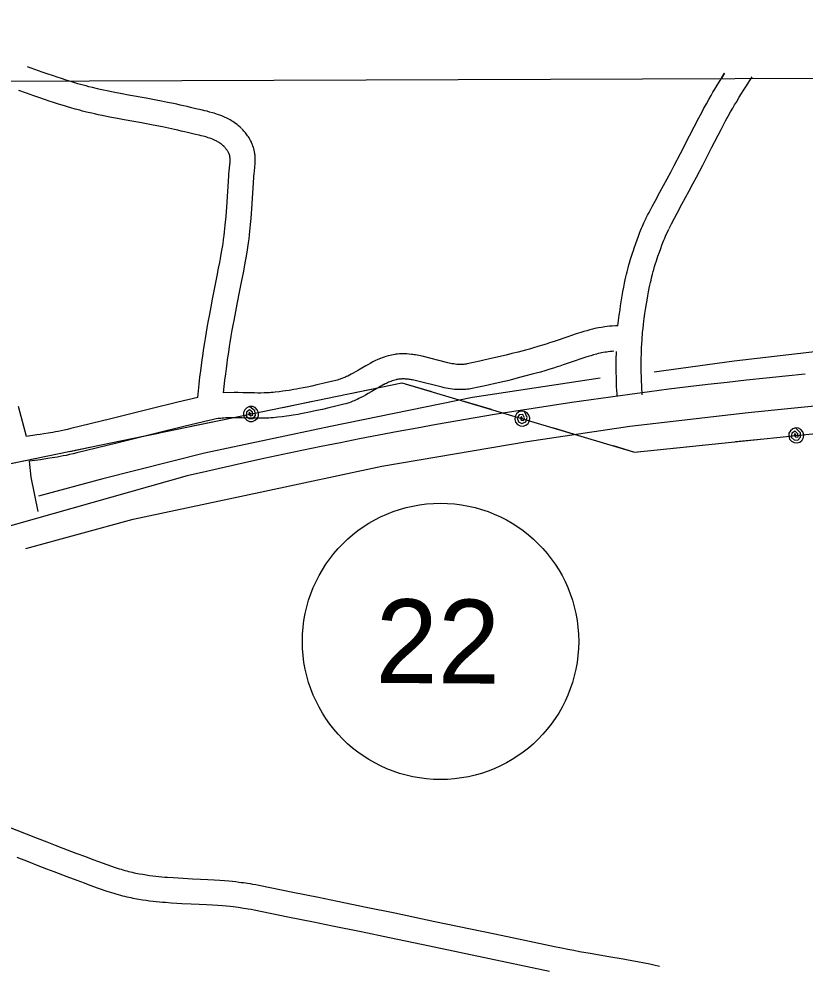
# Model space of a CAD drawing. Extents: x 3392644 to 3430565, y 576657 to 602123.
# Drawn here: x 3407890 to 3408829, y 599212 to 600343 of the extents above; entities that cross this region are included whole.
import ezdxf

# ---------------------------------------------------------------- set-up
doc = ezdxf.new("R2010")
doc.units = 0
for name, color, linetype in [('V-GRID-FRAM', 7, 'Continuous'), ('V-ROAD-CNTR', 7, 'Continuous'), ('V-ROAD-IDEN', 7, 'Continuous'), ('V-TOPO-SHOR', 7, 'Continuous'), ('V-UTIL-LINE', 7, 'Continuous')]:
    doc.layers.add(name, color=color, linetype=linetype)

msp = doc.modelspace()

# ---------------------------------------------------------------- linework, layer by layer
at = {"layer": 'V-GRID-FRAM'}
msp.add_lwpolyline([(3396720.3, 600227.7), (3428325.7, 600342.6), (3428399.7, 582159.3), (3396778.5, 582044.3), (3396720.3, 600227.7)], dxfattribs=at)
at = {"layer": 'V-ROAD-CNTR'}
for points in [[(3408156.2, 600211.8), (3408154.6, 600213.4), (3408152.8, 600215), (3408151, 600216.4), (3408149.3, 600217.7), (3408147.6, 600219), (3408145.9, 600220.1), (3408144.3, 600221.1), (3408142.7, 600222.1), (3408141.1, 600222.9), (3408139.6, 600223.7), (3408138.1, 600224.5), (3408136.7, 600225.1), (3408135.3, 600225.8), (3408132.7, 600226.9), (3408130.2, 600227.8), (3408127.8, 600228.7), (3408125.7, 600229.4), (3408123.6, 600230), (3408121.7, 600230.6), (3408118.2, 600231.5), (3408115.2, 600232.3), (3408112.6, 600232.9), (3408108.1, 600233.9), (3408101.7, 600235.3), (3408098.6, 600236.1), (3408095.5, 600236.8), (3408091.2, 600237.9), (3408087, 600238.9), (3408082.9, 600239.8), (3408079, 600240.7), (3408075.2, 600241.5), (3408067.8, 600243), (3408060.9, 600244.4), (3408054.4, 600245.7), (3408042.4, 600247.9), (3408021.5, 600251.7), (3408013.7, 600253.1), (3408006.9, 600254.4), (3408001.1, 600255.6), (3407995.9, 600256.7), (3407991.5, 600257.6), (3407987.6, 600258.5), (3407984.2, 600259.2), (3407978.3, 600260.6), (3407973.9, 600261.7), (3407970.6, 600262.6), (3407965.7, 600263.9), (3407960.8, 600265.3), (3407957.1, 600266.4), (3407953.6, 600267.4), (3407946.9, 600269.5), (3407941.2, 600271.4), (3407936.1, 600273), (3407931.7, 600274.5), (3407924, 600277.2), (3407918.2, 600279.2), (3407909.5, 600282.3), (3407900.8, 600285.5)], [(3408639.8, 600105.1), (3408641.3, 600108.2), (3408643.1, 600111.6), (3408646.8, 600118.8), (3408650.2, 600125), (3408656, 600135.7), (3408664.6, 600151.7), (3408668.9, 600159.7), (3408673.1, 600167.7), (3408680.5, 600181.8), (3408691.5, 600203.2), (3408702.6, 600224.6), (3408704.5, 600228.3), (3408706.4, 600231.8), (3408708.1, 600235.1), (3408711.5, 600241.2), (3408714.4, 600246.5), (3408717.1, 600251.1), (3408719.4, 600255.1), (3408721.5, 600258.6), (3408725.2, 600264.7), (3408728, 600269.2), (3408730.1, 600272.6), (3408733.3, 600277.7), (3408729.6, 600272)], [(3408667.4, 600093.2), (3408668.1, 600094.7), (3408669.7, 600097.8), (3408673.3, 600104.7), (3408676.6, 600110.8), (3408682.3, 600121.4), (3408691, 600137.5), (3408695.4, 600145.6), (3408699.7, 600153.8), (3408707.1, 600168), (3408718.2, 600189.4), (3408729.2, 600210.8), (3408731.1, 600214.4), (3408732.8, 600217.7), (3408734.5, 600220.8), (3408737.7, 600226.6), (3408740.5, 600231.7), (3408743.1, 600236.1), (3408745.3, 600239.9), (3408747.3, 600243.2), (3408750.8, 600249.1), (3408753.5, 600253.4), (3408755.5, 600256.7), (3408758.6, 600261.5), (3408766.3, 600273.6)], [(3408135.4, 600190.2), (3408134.3, 600191.3), (3408133.3, 600192.1), (3408132.4, 600192.9), (3408131.4, 600193.6), (3408130.5, 600194.3), (3408129.6, 600194.9), (3408128.7, 600195.5), (3408127.7, 600196), (3408126.8, 600196.5), (3408125.9, 600197), (3408125, 600197.5), (3408124.1, 600197.9), (3408123.3, 600198.3), (3408121.5, 600199), (3408119.8, 600199.7), (3408118.1, 600200.3), (3408116.5, 600200.8), (3408115, 600201.3), (3408113.5, 600201.7), (3408110.6, 600202.5), (3408108.1, 600203.1), (3408105.8, 600203.7), (3408101.5, 600204.6), (3408095, 600206.1), (3408091.7, 600206.9), (3408088.3, 600207.7), (3408084.2, 600208.7), (3408080.2, 600209.7), (3408076.3, 600210.5), (3408072.6, 600211.4), (3408068.9, 600212.2), (3408061.8, 600213.6), (3408055.1, 600215), (3408048.9, 600216.2), (3408037, 600218.4), (3408016, 600222.2), (3408008.1, 600223.7), (3408001.2, 600225), (3407995.1, 600226.2), (3407989.8, 600227.3), (3407985.1, 600228.3), (3407981, 600229.2), (3407977.5, 600230), (3407971.2, 600231.5), (3407966.5, 600232.6), (3407963, 600233.6), (3407957.7, 600235), (3407952.5, 600236.5), (3407948.5, 600237.6), (3407944.8, 600238.8), (3407937.9, 600240.9), (3407931.9, 600242.8), (3407926.6, 600244.6), (3407922, 600246.1), (3407914.1, 600248.8), (3407908.1, 600250.9), (3407899.3, 600254.1), (3407890.5, 600257.3)], [(3408134.7, 599896.3), (3408136.5, 599911.5), (3408137.4, 599918.9), (3408138.2, 599925.4), (3408139, 599931.1), (3408139.7, 599936.1), (3408141, 599944.9), (3408142, 599951.5), (3408142.8, 599956.4), (3408144.1, 599963.8), (3408145.3, 599971.2), (3408146.4, 599977.1), (3408147.4, 599982.6), (3408149.4, 599993.1), (3408151.1, 600002.2), (3408154.3, 600018.2), (3408156.7, 600030.2), (3408158.5, 600039.4), (3408159.7, 600046.2), (3408160.7, 600051.4), (3408162.1, 600059.2), (3408163.4, 600067.1), (3408163.8, 600069.9), (3408164.6, 600075.2), (3408165.3, 600080.2), (3408165.9, 600084.9), (3408166.3, 600089.2), (3408166.8, 600093.3), (3408167.1, 600097.2), (3408167.7, 600104.3), (3408168.2, 600110.5), (3408168.6, 600116), (3408170.9, 600153.2), (3408171.1, 600155.3), (3408171.3, 600157.3), (3408171.7, 600161.4), (3408172.2, 600165.2), (3408172.3, 600167.1), (3408172.5, 600168.8), (3408172.6, 600170.5), (3408172.7, 600172.2), (3408172.7, 600173.7), (3408172.7, 600175.3), (3408172.6, 600176.7), (3408172.6, 600178.1), (3408172.5, 600179.4), (3408172.3, 600180.7), (3408172.2, 600182), (3408171.8, 600184.1), (3408171.4, 600186.1), (3408170.9, 600187.9), (3408170.5, 600189.5), (3408170, 600190.9), (3408169.6, 600192.1), (3408169.1, 600193.2), (3408168.4, 600195), (3408167.7, 600196.4), (3408167.1, 600197.5), (3408166.3, 600199), (3408165.4, 600200.5), (3408164.5, 600201.8), (3408163.6, 600203.1), (3408162.7, 600204.3), (3408161.8, 600205.5), (3408160.9, 600206.6), (3408160, 600207.7), (3408159.1, 600208.8), (3408158.2, 600209.8), (3408157.3, 600210.7), (3408156.5, 600211.5)], [(3408104.1, 599890.8), (3408105.7, 599906.4), (3408106.2, 599910.8), (3408106.7, 599915), (3408107.6, 599922.6), (3408108.5, 599929.4), (3408109.3, 599935.3), (3408110, 599940.4), (3408111.3, 599949.4), (3408112.4, 599956.2), (3408113.2, 599961.2), (3408114.5, 599968.8), (3408115.8, 599976.3), (3408116.9, 599982.4), (3408117.9, 599988.1), (3408119.9, 599998.7), (3408121.7, 600008), (3408124.9, 600024), (3408127.3, 600036), (3408129, 600045), (3408130.2, 600051.7), (3408131.2, 600056.7), (3408132.5, 600064.3), (3408133.8, 600071.9), (3408134.2, 600074.4), (3408134.9, 600079.4), (3408135.5, 600084), (3408136.1, 600088.3), (3408136.5, 600092.4), (3408136.9, 600096.3), (3408137.2, 600099.9), (3408137.8, 600106.7), (3408138.3, 600112.7), (3408138.6, 600117.9), (3408141, 600155.4), (3408141.2, 600158.1), (3408141.4, 600160.6), (3408141.9, 600164.8), (3408142.3, 600168.3), (3408142.5, 600169.7), (3408142.6, 600170.9), (3408142.6, 600172), (3408142.7, 600173), (3408142.7, 600173.9), (3408142.7, 600174.8), (3408142.7, 600175.5), (3408142.6, 600176.1), (3408142.6, 600176.7), (3408142.5, 600177.3), (3408142.5, 600177.7), (3408142.3, 600178.7), (3408142.2, 600179.4), (3408142, 600180), (3408141.8, 600180.6), (3408141.7, 600181), (3408141.5, 600181.4), (3408141.4, 600181.7), (3408141.1, 600182.4), (3408140.9, 600182.9), (3408140.7, 600183.2), (3408140.4, 600183.8), (3408140, 600184.4), (3408139.6, 600185.1), (3408139.1, 600185.8), (3408138.6, 600186.5), (3408138.1, 600187.1), (3408137.6, 600187.7), (3408137.1, 600188.3), (3408136.7, 600188.9), (3408136.2, 600189.4), (3408135.7, 600189.9), (3408135.1, 600190.5)], [(3408605.9, 599976.3), (3408607.5, 599989), (3408608.4, 599995.3), (3408609.1, 600000.1), (3408610.2, 600007.2), (3408611.4, 600014.3), (3408611.9, 600017.2), (3408612.9, 600022.5), (3408613.8, 600027.1), (3408614.7, 600031.2), (3408615.5, 600034.8), (3408616.2, 600037.9), (3408616.9, 600040.6), (3408618.1, 600045.3), (3408619.1, 600048.9), (3408619.8, 600051.6), (3408621, 600055.6), (3408622.2, 600059.5), (3408623.3, 600062.9), (3408624.3, 600066), (3408625.2, 600068.9), (3408627.1, 600074.3), (3408628.8, 600079), (3408630.4, 600083.1), (3408631.8, 600086.7), (3408633, 600089.9), (3408634.2, 600092.6), (3408635.2, 600095), (3408637, 600099.2), (3408638.5, 600102.3), (3408639.6, 600104.7), (3408639.8, 600105.1)], [(3408636.4, 599977.9), (3408636.8, 599981.6), (3408637.3, 599985.1), (3408638.1, 599991.1), (3408638.8, 599995.6), (3408639.9, 600002.4), (3408641, 600009.3), (3408641.4, 600011.9), (3408642.4, 600016.8), (3408643.2, 600021.1), (3408644, 600024.8), (3408644.7, 600028.1), (3408645.4, 600030.9), (3408646, 600033.4), (3408647.1, 600037.7), (3408648, 600040.9), (3408648.6, 600043.3), (3408649.7, 600046.9), (3408650.8, 600050.6), (3408651.8, 600053.6), (3408652.8, 600056.5), (3408653.7, 600059.2), (3408655.4, 600064.3), (3408657, 600068.6), (3408658.4, 600072.4), (3408659.7, 600075.7), (3408660.8, 600078.5), (3408661.8, 600081), (3408662.7, 600083.1), (3408664.4, 600086.8), (3408665.7, 600089.6), (3408666.6, 600091.6), (3408666.6, 600091.7)], [(3408666.9, 600092.2), (3408667.4, 600093.2)], [(3408634.1, 599947.3), (3408634.2, 599950), (3408634.5, 599954.7), (3408634.7, 599959.5), (3408634.9, 599962.5), (3408635.2, 599965.4), (3408635.4, 599968.1), (3408635.9, 599973.3), (3408636.4, 599977.7), (3408636.4, 599977.9)], [(3408605.9, 599976.3), (3408602.8, 599976.2), (3408599, 599975.9), (3408595.8, 599975.6), (3408592.9, 599975.2), (3408590.4, 599974.9), (3408588.2, 599974.6), (3408586.2, 599974.3), (3408582.8, 599973.7), (3408580.2, 599973.2), (3408578.3, 599972.8), (3408575.4, 599972.1), (3408572.5, 599971.4), (3408568.6, 599970.4), (3408565, 599969.3), (3408561.7, 599968.3), (3408558.7, 599967.4), (3408555.8, 599966.5), (3408550.6, 599964.7), (3408546.1, 599963.2), (3408530.8, 599957.9), (3408527, 599956.6), (3408524.2, 599955.7), (3408520, 599954.3), (3408515.8, 599953), (3408510.2, 599951.4), (3408505, 599949.9), (3408500.1, 599948.5), (3408495.5, 599947.3), (3408486.8, 599944.9), (3408479.2, 599943), (3408472.5, 599941.3), (3408466.7, 599939.9), (3408461.6, 599938.7), (3408452.6, 599936.6), (3408445.9, 599935), (3408440.9, 599933.9), (3408433.3, 599932.3), (3408425.8, 599930.7), (3408424.8, 599930.5), (3408423.8, 599930.4), (3408422.9, 599930.3), (3408421.9, 599930.2), (3408421, 599930.1), (3408420.1, 599930), (3408419.1, 599930), (3408418.2, 599930), (3408417.2, 599930), (3408416.3, 599930), (3408415.4, 599930.1), (3408413.5, 599930.2), (3408411.6, 599930.4), (3408409.8, 599930.7), (3408408, 599931), (3408406.1, 599931.3), (3408404.4, 599931.6), (3408402.8, 599932), (3408372.2, 599939.9), (3408369.9, 599940.4), (3408367.9, 599940.8), (3408366, 599941.1), (3408364.2, 599941.5), (3408362.5, 599941.7), (3408360.9, 599941.9), (3408359.3, 599942.1), (3408356.5, 599942.4), (3408353.9, 599942.6), (3408351.7, 599942.7), (3408349.7, 599942.7), (3408347.9, 599942.7), (3408346.3, 599942.7), (3408344.9, 599942.6), (3408342.6, 599942.4), (3408340.8, 599942.2), (3408339.3, 599942), (3408337.3, 599941.7), (3408335.3, 599941.3), (3408333.8, 599940.9), (3408331.3, 599940.3), (3408328.8, 599939.5), (3408326.5, 599938.8), (3408324.3, 599938), (3408322.3, 599937.2)], [(3408601, 599945.9), (3408598.9, 599945.7), (3408596.5, 599945.4), (3408594.4, 599945.2), (3408592.6, 599944.9), (3408591, 599944.7), (3408588.2, 599944.2), (3408586.2, 599943.8), (3408584.7, 599943.5), (3408582.4, 599943), (3408580.1, 599942.4), (3408576.7, 599941.5), (3408573.5, 599940.5), (3408570.5, 599939.6), (3408567.7, 599938.8), (3408565.1, 599937.9), (3408560.2, 599936.3), (3408555.9, 599934.8), (3408540.5, 599929.5), (3408536.5, 599928.1), (3408533.5, 599927.1), (3408529, 599925.7), (3408524.4, 599924.3), (3408518.6, 599922.6), (3408513.2, 599921), (3408508.1, 599919.6), (3408503.3, 599918.3), (3408494.4, 599915.9), (3408486.6, 599913.9), (3408479.8, 599912.2), (3408473.8, 599910.7), (3408468.5, 599909.5), (3408459.3, 599907.3), (3408452.4, 599905.8), (3408447.3, 599904.6), (3408439.5, 599903), (3408431.7, 599901.3), (3408429.9, 599901), (3408428.2, 599900.7), (3408426.4, 599900.5), (3408424.7, 599900.3), (3408423, 599900.2), (3408421.4, 599900.1), (3408419.8, 599900), (3408418.2, 599900), (3408416.6, 599900), (3408415.1, 599900.1), (3408413.6, 599900.1), (3408410.8, 599900.3), (3408408.1, 599900.6), (3408405.5, 599901), (3408403, 599901.4), (3408400.6, 599901.8), (3408398.3, 599902.2), (3408395.9, 599902.8), (3408365.2, 599910.7), (3408363.7, 599911), (3408362.1, 599911.3), (3408360.7, 599911.6), (3408359.3, 599911.8), (3408358.1, 599912), (3408356.9, 599912.2), (3408355.9, 599912.3), (3408353.9, 599912.5), (3408352.2, 599912.6), (3408350.8, 599912.7), (3408349.6, 599912.7), (3408348.5, 599912.7), (3408347.6, 599912.7), (3408346.9, 599912.6), (3408345.5, 599912.5), (3408344.5, 599912.4), (3408343.8, 599912.3), (3408342.7, 599912.1), (3408341.6, 599911.9), (3408340.9, 599911.8), (3408339.3, 599911.3), (3408337.8, 599910.9), (3408336.3, 599910.4), (3408334.8, 599909.9), (3408333.3, 599909.3)], [(3408605.1, 599891.8), (3408604.8, 599895.4), (3408604.6, 599898.6), (3408604.3, 599904.1), (3408604.2, 599908.4), (3408604, 599914.6), (3408603.8, 599920.8), (3408603.8, 599925.9), (3408603.8, 599930.3), (3408603.8, 599934.2), (3408603.8, 599937.6), (3408604, 599943.5), (3408604, 599945.7)], [(3408635, 599893.9), (3408634.8, 599897.4), (3408634.6, 599900.3), (3408634.3, 599905.6), (3408634.1, 599909.5), (3408633.9, 599915.4), (3408633.8, 599921.3), (3408633.8, 599926.1), (3408633.8, 599930.3), (3408633.8, 599933.9), (3408633.8, 599937.1), (3408634, 599942.7), (3408634.1, 599946.9), (3408634.1, 599947.3)], [(3408319.3, 599935.9), (3408318.3, 599935.5), (3408316.5, 599934.6), (3408314.8, 599933.8), (3408313.1, 599933), (3408310, 599931.4), (3408307.2, 599929.8), (3408304.6, 599928.3), (3408299.9, 599925.6), (3408296, 599923.3), (3408292.6, 599921.3), (3408289.7, 599919.6), (3408287.2, 599918.3), (3408285.1, 599917.1), (3408283.3, 599916.2), (3408281.7, 599915.5), (3408280.3, 599914.8), (3408279.1, 599914.3), (3408278.1, 599913.9), (3408276.3, 599913.2), (3408274.9, 599912.7), (3408274, 599912.4), (3408272.5, 599911.9), (3408270.9, 599911.5), (3408261.7, 599909.2), (3408253.5, 599907.3), (3408246.3, 599905.6), (3408240.1, 599904.2), (3408234.6, 599903.1), (3408229.8, 599902.1), (3408225.6, 599901.3), (3408222, 599900.6), (3408218.8, 599900), (3408213.2, 599899.1), (3408209, 599898.4), (3408205.8, 599898), (3408201.1, 599897.3), (3408196.4, 599896.8), (3408194.1, 599896.5), (3408191.9, 599896.4), (3408189.7, 599896.2), (3408187.6, 599896.1), (3408185.5, 599896), (3408183.5, 599896), (3408179.4, 599895.9), (3408175.6, 599895.9), (3408172, 599896), (3408157.8, 599896.3), (3408152.4, 599896.4), (3408147.5, 599896.4), (3408134.7, 599896.3)], [(3408322, 599937.1), (3408320.2, 599936.3), (3408319.3, 599935.9)], [(3408333.6, 599909.4), (3408332, 599908.8), (3408330.7, 599908.2), (3408329.3, 599907.5), (3408328, 599906.9), (3408326.8, 599906.3), (3408326.2, 599906)], [(3408326.2, 599906), (3408324.2, 599904.9), (3408321.8, 599903.6), (3408319.6, 599902.3), (3408315.1, 599899.7), (3408311.2, 599897.4), (3408307.6, 599895.3), (3408304.4, 599893.5), (3408301.4, 599891.9), (3408298.8, 599890.5), (3408296.5, 599889.3), (3408294.4, 599888.3), (3408292.5, 599887.4), (3408290.9, 599886.7), (3408289.3, 599886.1), (3408286.7, 599885.1), (3408284.7, 599884.3), (3408283.1, 599883.8), (3408280.8, 599883.1), (3408278.4, 599882.5), (3408268.8, 599880.1), (3408260.4, 599878.1), (3408252.9, 599876.3), (3408246.4, 599874.9), (3408240.7, 599873.7), (3408235.6, 599872.7), (3408231.2, 599871.8), (3408227.3, 599871.1), (3408223.9, 599870.5), (3408217.9, 599869.5), (3408213.4, 599868.8), (3408210, 599868.3), (3408204.9, 599867.6), (3408199.8, 599867), (3408196.9, 599866.7), (3408194.2, 599866.4), (3408191.5, 599866.3), (3408188.9, 599866.1), (3408186.5, 599866), (3408184.1, 599866), (3408179.6, 599865.9), (3408175.3, 599865.9), (3408171.4, 599866), (3408157.2, 599866.3), (3408152, 599866.4), (3408147.6, 599866.4), (3408143.8, 599866.4), (3408140.5, 599866.3), (3408137.7, 599866.2), (3408135.3, 599866), (3408133.2, 599865.9), (3408131.4, 599865.7), (3408129.8, 599865.5), (3408128.5, 599865.4), (3408126, 599865), (3408124.3, 599864.7), (3408123, 599864.5), (3408121.1, 599864.1), (3408119.1, 599863.6), (3408087.2, 599855.8), (3408055.3, 599848), (3408007.5, 599836.2), (3407959.6, 599824.4), (3407955.1, 599823.3), (3407950.9, 599822.4), (3407946.9, 599821.5), (3407943.1, 599820.8), (3407939.6, 599820.1), (3407936.4, 599819.5), (3407930.3, 599818.4), (3407924.9, 599817.6), (3407920.2, 599816.8), (3407916.1, 599816.2), (3407903.1, 599814.4)], [(3408104.1, 599890.8), (3408080.1, 599885), (3408048.1, 599877.1), (3408000.3, 599865.3), (3407952.5, 599853.5), (3407948.4, 599852.5), (3407944.5, 599851.7), (3407940.8, 599850.9), (3407937.4, 599850.2), (3407934.1, 599849.6), (3407931.1, 599849), (3407925.3, 599848), (3407920.2, 599847.2), (3407915.7, 599846.5), (3407911.8, 599845.9), (3407899.5, 599844.2)], [(3407899.5, 599844.2), (3407890.1, 599880)], [(3407913.6, 599754.4), (3407905.2, 599795.3), (3407903.1, 599814.4)], [(3408091.5, 599797), (3407590.4, 599655.2)], [(3407863.4, 599383.4), (3407898.9, 599369.6), (3407912.2, 599364.5), (3407923.8, 599360), (3407933.9, 599356.1), (3407942.8, 599352.6), (3407958.4, 599346.7), (3407970.1, 599342.4), (3407978.9, 599339.1), (3407985.5, 599336.7), (3407995.4, 599333.1), (3408005.3, 599329.6), (3408007.7, 599328.8), (3408010, 599328), (3408012.4, 599327.3), (3408014.7, 599326.6), (3408017, 599325.9), (3408019.2, 599325.3), (3408021.4, 599324.8), (3408023.6, 599324.2), (3408025.8, 599323.7), (3408028, 599323.2), (3408030.1, 599322.8), (3408032.2, 599322.4), (3408034.3, 599322), (3408038.4, 599321.3), (3408042.5, 599320.6), (3408046.4, 599320), (3408050.2, 599319.5), (3408053.9, 599319.1), (3408057.6, 599318.7), (3408061.1, 599318.4), (3408064.6, 599318), (3408067.9, 599317.8), (3408074.5, 599317.3), (3408080.7, 599316.9), (3408086.5, 599316.6), (3408097.6, 599316), (3408107.4, 599315.5), (3408115.9, 599315.1), (3408123.5, 599314.7), (3408130.2, 599314.2), (3408136, 599313.8), (3408141.1, 599313.3), (3408145.6, 599312.9), (3408149.6, 599312.5), (3408153, 599312.1), (3408156, 599311.7), (3408158.7, 599311.4), (3408163.3, 599310.7), (3408166.8, 599310.2), (3408169.4, 599309.7), (3408173.3, 599309), (3408177.1, 599308.3), (3408217.7, 599300), (3408248.1, 599293.9), (3408271, 599289.2), (3408305.2, 599282.2), (3408339.4, 599275.1), (3408387.1, 599265.1), (3408458.7, 599250.1), (3408494.5, 599242.6), (3408530.3, 599235.1), (3408538.4, 599233.4), (3408546.1, 599231.9), (3408553.3, 599230.6), (3408560, 599229.3), (3408572.7, 599227), (3408595.1, 599223.1), (3408612, 599220.2), (3408618.3, 599219), (3408629.4, 599217), (3408637.8, 599215.4), (3408644, 599214.2), (3408648.8, 599213.2), (3408655.7, 599211.7)], [(3407888, 599341.7), (3407901.3, 599336.5), (3407913, 599332), (3407923.2, 599328), (3407932.1, 599324.6), (3407947.8, 599318.7), (3407959.6, 599314.2), (3407968.5, 599311), (3407975.2, 599308.5), (3407985.2, 599304.9), (3407995.4, 599301.3), (3407998.1, 599300.3), (3408000.9, 599299.4), (3408003.6, 599298.6), (3408006.3, 599297.8), (3408009, 599297), (3408011.6, 599296.3), (3408014.2, 599295.6), (3408016.7, 599295), (3408019.2, 599294.5), (3408021.7, 599293.9), (3408024.1, 599293.4), (3408026.5, 599292.9), (3408028.9, 599292.5), (3408033.5, 599291.7), (3408037.9, 599291), (3408042.3, 599290.3), (3408046.5, 599289.8), (3408050.6, 599289.3), (3408054.5, 599288.9), (3408058.3, 599288.5), (3408062, 599288.2), (3408065.6, 599287.9), (3408072.4, 599287.4), (3408078.9, 599286.9), (3408084.9, 599286.6), (3408096.1, 599286), (3408105.9, 599285.6), (3408114.3, 599285.1), (3408121.7, 599284.7), (3408128.1, 599284.3), (3408133.6, 599283.9), (3408138.4, 599283.5), (3408142.6, 599283.1), (3408146.3, 599282.7), (3408149.5, 599282.3), (3408152.2, 599282), (3408154.6, 599281.7), (3408158.8, 599281), (3408162, 599280.6), (3408164.3, 599280.2), (3408167.8, 599279.5), (3408171.3, 599278.9), (3408211.8, 599270.6), (3408242.2, 599264.5), (3408264.9, 599259.8), (3408299.1, 599252.8), (3408333.2, 599245.7), (3408381, 599235.8), (3408452.6, 599220.7), (3408488.4, 599213.2), (3408524.2, 599205.7)]]:
    msp.add_lwpolyline(points, dxfattribs=at)
msp.add_arc((3409364.6, 594364.7), 5579.5, 95.5044, 103.1898, dxfattribs=at)
at = {"layer": 'V-ROAD-IDEN'}
msp.add_circle((3408394, 599599.4), 165, dxfattribs=at)
at = {"layer": 'V-TOPO-SHOR'}
for points in [[(3409037.3, 599964.5), (3408913.3, 599953.4), (3408744.9, 599934.1), (3408649.1, 599920.8)], [(3407898.7, 599710.2), (3408026.8, 599745.5), (3408178.7, 599777.6), (3408323.9, 599808.8), (3408497.3, 599838.2), (3408619.9, 599856.3), (3408761.6, 599872.8), (3408919.5, 599888.6), (3409072.5, 599902.9), (3409211.8, 599917.1), (3409342.4, 599929.4), (3409378.8, 599933.1)], [(3408584.7, 599913.6), (3408432.2, 599890.5), (3408262.4, 599856), (3408112.1, 599824), (3407990.7, 599793.5), (3407913.7, 599772.8)]]:
    msp.add_lwpolyline(points, dxfattribs=at)
at = {"layer": 'V-UTIL-LINE'}
for points in [[(3402959.7, 600250.4), (3404204.9, 598822.1), (3404726.9, 598250.3), (3405207.5, 598516.1), (3406263.4, 599099.6), (3406784.2, 599391.3), (3407290.1, 599621), (3407808.9, 599797), (3408347.9, 599908.1), (3408625.7, 599825.5), (3409274.7, 599892), (3409932, 599953.2), (3410526.5, 600014.5), (3411179, 600074.5), (3411843.5, 600129.7), (3412525.8, 600199.3), (3413442.4, 600288.5)], [(3408278.3, 599893.7), (3408311.6, 599900.6)], [(3408350.7, 599907.2), (3408383.3, 599897.6)], [(3408167.7, 599870.9), (3408165.6, 599872.9), (3408165.2, 599870.6), (3408167.3, 599868.8), (3408170, 599869.7), (3408169.5, 599873), (3408165.7, 599875.7), (3408162.2, 599873.2), (3408161.9, 599868.3), (3408165.6, 599865.6), (3408170.1, 599865.6), (3408173.1, 599869.3), (3408172.3, 599874.8), (3408165.8, 599879.7), (3408162.6, 599878.4), (3408160.1, 599875.9), (3408158.8, 599872.6), (3408158.8, 599869.1), (3408160.2, 599865.9), (3408162.7, 599863.4), (3408166, 599862.1), (3408169.5, 599862.1), (3408172.7, 599863.5), (3408175.2, 599866), (3408176.5, 599869.2), (3408176.5, 599872.8), (3408175.1, 599876), (3408172.6, 599878.5), (3408169.4, 599879.8), (3408165.8, 599879.7)], [(3408205.8, 599878.8), (3408239.1, 599885.7)], [(3408421.7, 599886.2), (3408454.3, 599876.5)], [(3408491.7, 599865.4), (3408490.8, 599868.1), (3408489.4, 599866.2), (3408490.3, 599863.7), (3408493.2, 599863.1), (3408494.3, 599866.3), (3408492.2, 599870.5), (3408487.9, 599869.9), (3408485.4, 599865.8), (3408487.3, 599861.7), (3408491.2, 599859.5), (3408495.7, 599861.4), (3408497.6, 599866.6), (3408494.2, 599874), (3408490.7, 599874.3), (3408487.4, 599873.3), (3408484.7, 599871), (3408483, 599867.9), (3408482.7, 599864.4), (3408483.7, 599861.1), (3408486, 599858.4), (3408489.1, 599856.7), (3408492.6, 599856.4), (3408495.9, 599857.5), (3408498.6, 599859.7), (3408500.3, 599862.8), (3408500.6, 599866.3), (3408499.6, 599869.7), (3408497.3, 599872.4), (3408494.2, 599874)], [(3408096.2, 599856.2), (3408129.5, 599863.1)], [(3408529, 599854.3), (3408561.6, 599844.6)], [(3408818.9, 599845.3), (3408817, 599847.5), (3408816.4, 599845.2), (3408818.2, 599843.2), (3408821.1, 599843.8), (3408820.9, 599847.2), (3408817.4, 599850.3), (3408813.7, 599848.1), (3408812.9, 599843.3), (3408816.3, 599840.2), (3408820.7, 599839.7), (3408824.1, 599843.1), (3408823.9, 599848.6), (3408817.9, 599854.3), (3408814.6, 599853.2), (3408811.9, 599851), (3408810.2, 599847.9), (3408809.9, 599844.4), (3408810.9, 599841), (3408813.2, 599838.3), (3408816.3, 599836.7), (3408819.8, 599836.3), (3408823.1, 599837.4), (3408825.8, 599839.6), (3408827.5, 599842.7), (3408827.8, 599846.2), (3408826.8, 599849.6), (3408824.5, 599852.3), (3408821.4, 599853.9), (3408817.9, 599854.3)], [(3408023.7, 599841.3), (3408057, 599848.1)], [(3407951.2, 599826.3), (3407984.5, 599833.2)], [(3408600, 599833.2), (3408625.7, 599825.5), (3408632.8, 599826.3)], [(3408672.6, 599830.3), (3408706.4, 599833.8)], [(3408746.2, 599837.9), (3408780, 599841.3)], [(3407878.7, 599811.4), (3407912, 599818.2)]]:
    msp.add_lwpolyline(points, dxfattribs=at)

# ---------------------------------------------------------------- texts
at = {"layer": 'V-ROAD-IDEN'}
msp.add_text('22', height=100, rotation=359.6859, dxfattribs=at).set_placement((3408316.2, 599549.8))

doc.saveas('drawing.dxf')
